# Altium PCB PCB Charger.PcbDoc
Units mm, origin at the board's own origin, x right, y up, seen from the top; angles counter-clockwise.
Board outline 70.24 x 66.94 mm, 2 copper layers (Top Layer, Bottom Layer), stack 1.57 mm thick; 196 components, 95 nets, 576 pads, 0 vias.
Unrouted connection lines stored in the file: 426.
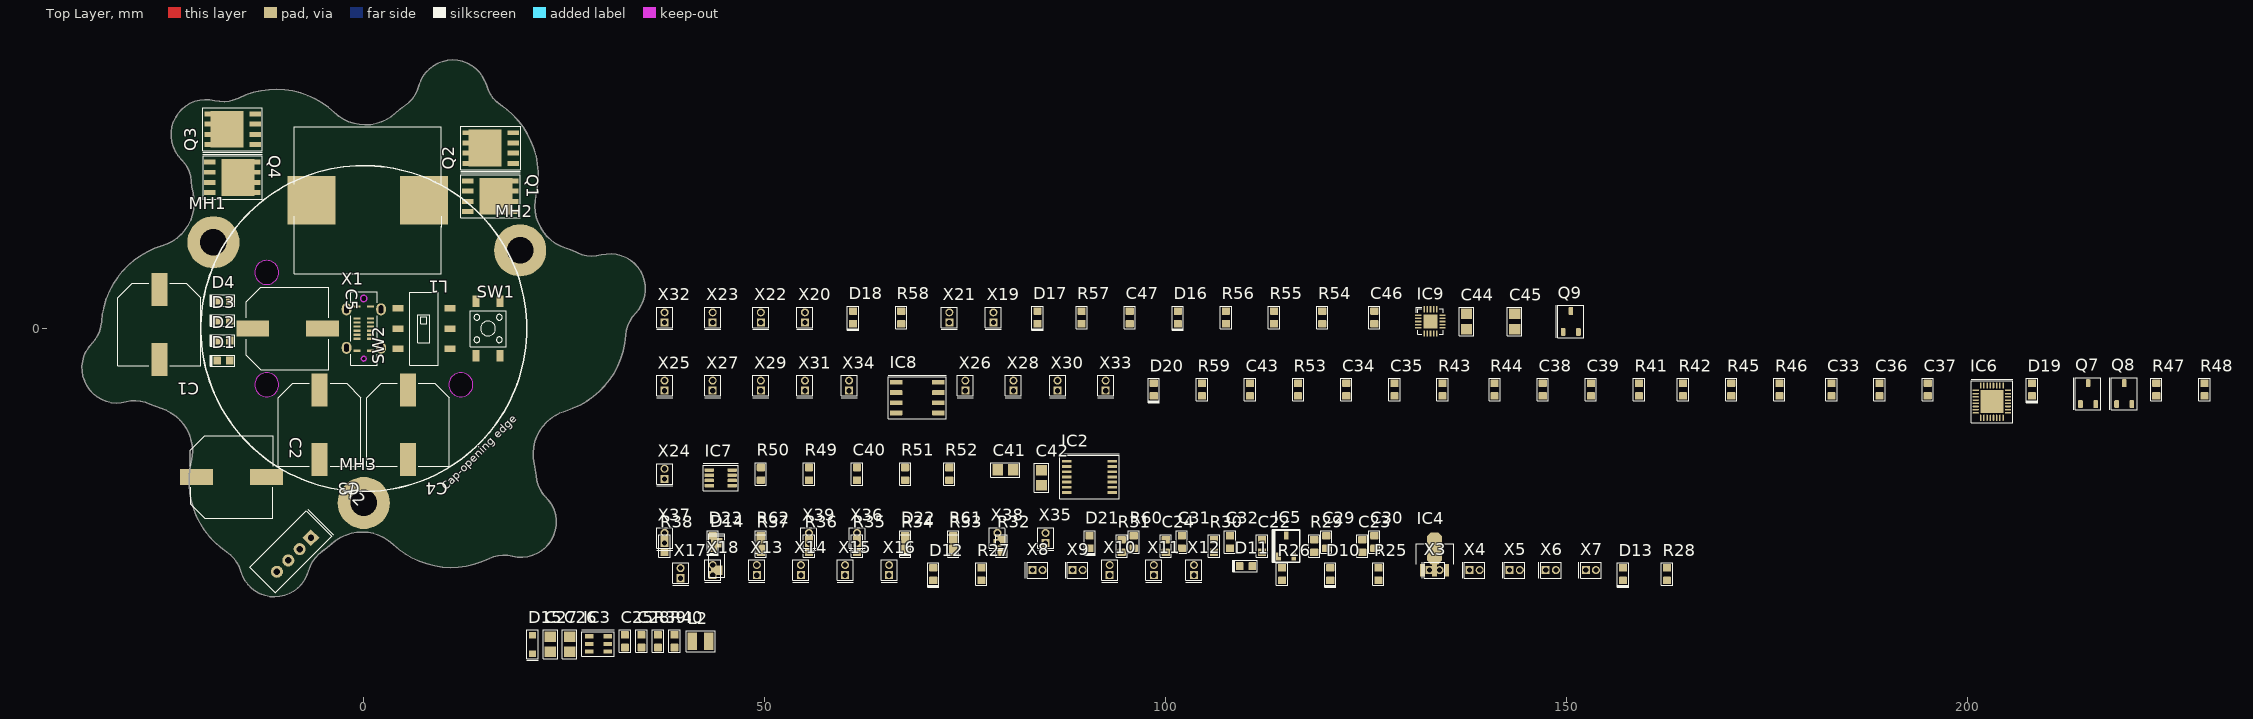
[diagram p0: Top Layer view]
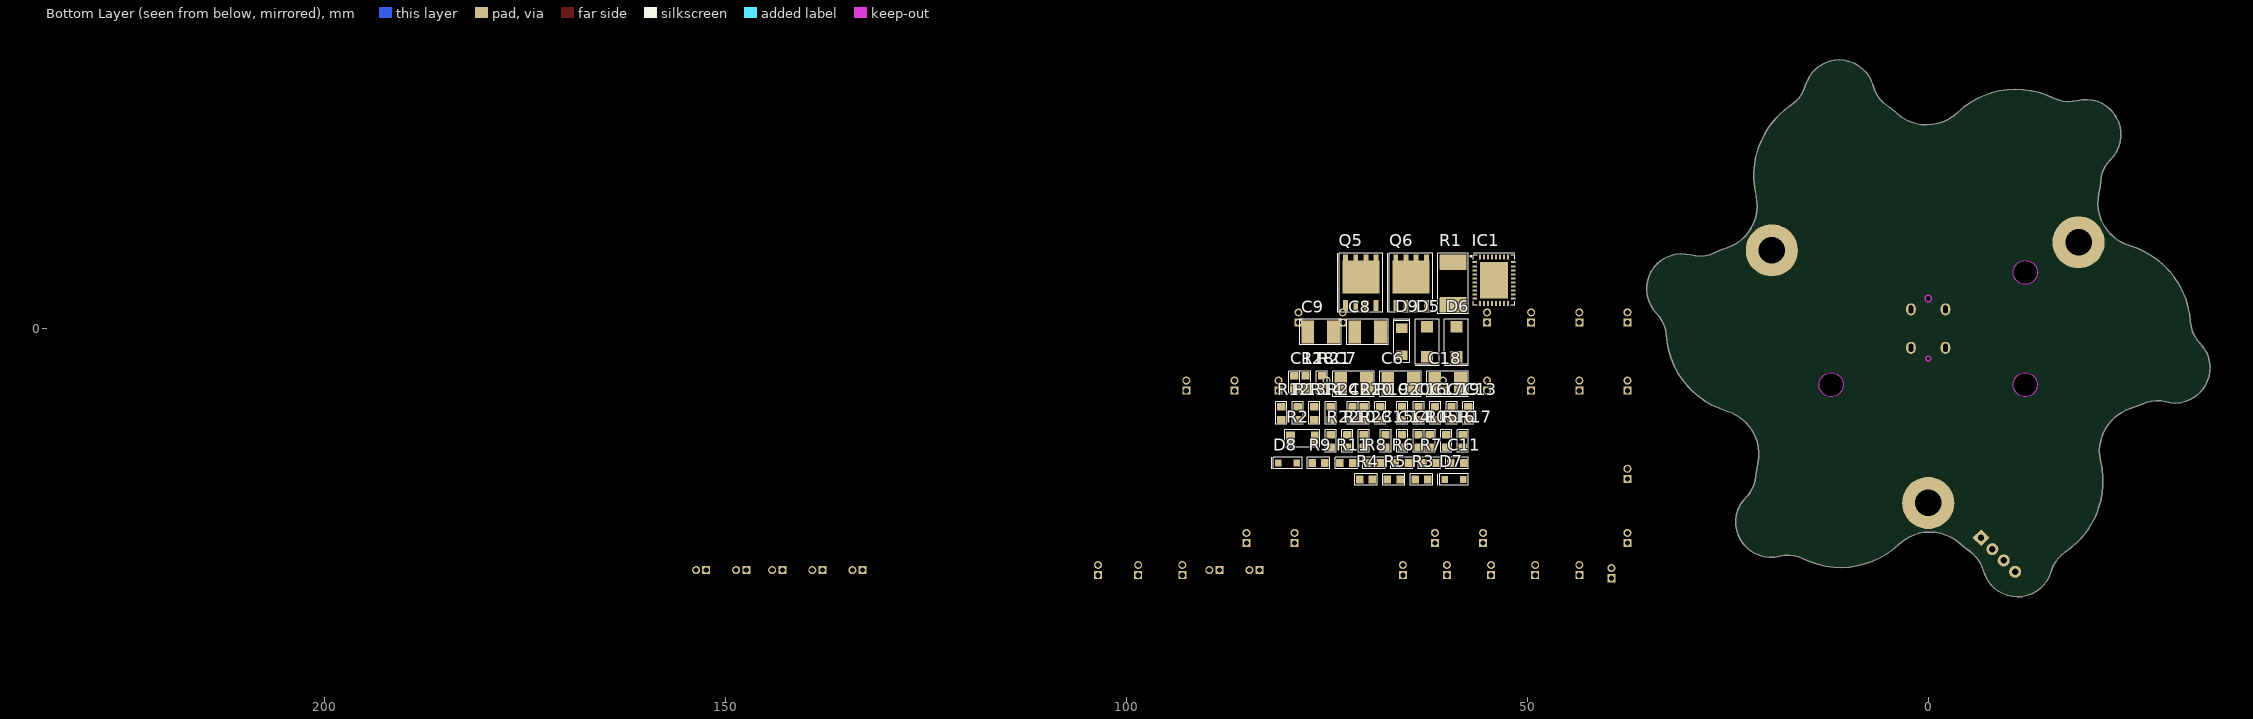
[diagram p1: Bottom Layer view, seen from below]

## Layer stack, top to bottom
Top Solder: solder mask 0.0102, Solder Resist, Dk 3.5
Top Layer: signal copper 0.0356
Dielectric 1: core 1.4986, Core-043, Dk 4.3
Bottom Layer: signal copper 0.0356
Bottom Solder: solder mask 0.0102, Solder Resist, Dk 3.5

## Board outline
331 vertices, not listed, extent -35.137,-33.454 35.107,33.486
cut-out: 10.61,-6.994 ccw(c12.11,-6.994) 12.11,-8.494 ccw(c12.11,-6.994) 13.61,-6.994 ccw(c12.11,-6.994) 12.11,-5.494 ccw(c12.11,-6.994)
cut-out: -13.61,6.994 ccw(c-12.11,6.994) -12.11,5.494 ccw(c-12.11,6.994) -10.61,6.994 ccw(c-12.11,6.994) -12.11,8.494 ccw(c-12.11,6.994)
cut-out: -13.609,-6.996 ccw(c-12.109,-6.996) -12.109,-8.496 ccw(c-12.109,-6.996) -10.609,-6.996 ccw(c-12.109,-6.996) -12.109,-5.496 ccw(c-12.109,-6.996)

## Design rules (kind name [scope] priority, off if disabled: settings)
Clearance [All] p1: gap=0.254 ignorepadtopadclearanceinfootprint=FALSE
PolygonConnect [All] p1: connectstyle=Relief reliefconductorwidth=0.254 reliefentries=4 polygonreliefangle="90 Angle" airgapwidth=0.254
RoutingVias [All] p1: holewidth=0.711 width=1.27 viastyle="Through Hole" minholewidth=0.711 minwidth=1.27 maxholewidth=0.711 maxwidth=1.27
SolderMaskExpansion [All] p1: expansion=0.102 istentingtop=FALSE
SupplyNets "Schematic Supply Nets_5" [InNet('LDO_3V3')] p1: voltage=0.000
SupplyNets "Schematic Supply Nets_4" [InNet('5V_SoC')] p2: voltage=0.000
SupplyNets "Schematic Supply Nets_3" [InNet('12V')] p3: voltage=0.000
SupplyNets "Schematic Supply Nets_2" [InNet('5V')] p4: voltage=0.000
SupplyNets "Schematic Supply Nets_1" [InNet('3V3')] p5: voltage=0.000
SupplyNets "Schematic Supply Nets" [InNet('GND')] p6: voltage=0.000
Width [All] p1: maxlimit=0.254 minlimit=0.254 preferedwidth=0.254
30 further rules are at their usual default settings.

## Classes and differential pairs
component class "USB PROTECTION": C44 C45 C46 C47 D16 D17 D18 IC9 Q9 R54 R55 R56 R57 R58 X19 X20 X21 X22 X23 X32
component class "USB PD": C33 C34 C35 C36 C37 C38 C39 C43 D19 D20 IC6 IC8 Q7 Q8 R41 R42 R43 R44 R45 R46 R47 R48 R53 R59 X25 X26 X27 X28 X29 X30 X31 X33 X34
component class "POWER PATH SWITCH": C40 C41 C42 IC7 Q5 Q6 R49 R50 R51 R52 X24
component class "POWER DISTRIBUTION": C25 C26 C27 C28 C29 C30 C31 C32 D15 D21 D22 D23 IC3 IC4 IC5 L2 R39 R40 R60 R61 R62 X35 X36 X37 X38 X39
component class "BATTERY LEVEL INDICATOR": C22 C23 C24 D14 IC2 R29 R30 R31 R32 R33 R34 R35 R36 R37 R38
component class CHARGER: C1 C2 C3 C4 C5 C6 C7 C8 C9 C10 C11 C12 C13 C14 C15 C16 C17 C18 C19 C20 C21 D5 D6 D7 D8 D9 D10 D11 D12 D13 IC1 L1 Q1 Q2 Q3 Q4 R1 R2 R3 R4 R5 R6 R7 R8 R9 R10 R11 R12 R13 R14 R15 R16 R17 R18 R19 R20 R21 R22 R23 R24 R25 R26 R27 R28 X3 X4 X5 X6 X7 X8 X9 X10 X11 X12 X13 X14 X15 X16 X17 X18
component class Arhitecture: D1 D2 D3 D4 MH1 MH2 MH3 SW1 SW2 X1 X2

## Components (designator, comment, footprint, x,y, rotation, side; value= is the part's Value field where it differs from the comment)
C1 "EEHZA1J560P" CAP_SMD_10X10.2 -25.5,0.5 r270 top
C2 "EEHZA1J560P" CAP_SMD_10X10.2 -16.5,-18.5 r0 top
C3 "EEHZA1J560P" CAP_SMD_10X10.2 -5.5,-12 r270 top
C4 "EEHZA1J560P" CAP_SMD_10X10.2 5.5,-12 r270 top
C5 "EEHZA1J560P" CAP_SMD_10X10.2 -9.5,0 r0 top
C6 "HMK325C7475KN-TE" CAP_1210 65.787,-6.899 r180 bottom
C7 "HMK325C7475KN-TE" CAP_1210 71.645,-6.899 r180 bottom
C8 "HMK325C7475KN-TE" CAP_1210 69.903,-0.441 r180 bottom
C9 "HMK325C7475KN-TE" CAP_1210 75.761,-0.441 r180 bottom
C10 "CL10A106MA8NRNC" "CAP 0603" 63.538,-14.015 r90 bottom
C11 "CL10A106MA8NRNC" "CAP 0603" 58.729,-16.773 r180 bottom
C12 "CC0603KRX7R0BB104" "CAP 0603" 79.054,-6.699 r90 bottom
C13 "CC0603KRX7R0BB104" "CAP 0603" 57.364,-10.557 r90 bottom
C14 "CC0603KRX7R0BB104" "CAP 0603" 65.596,-14.015 r90 bottom
C15 "CC0603KRX7R0BB104" "CAP 0603" 67.654,-14.015 r90 bottom
C16 "CL10B474KA8NNNC" "CAP 0603" 63.538,-10.557 r90 bottom
C17 "CL10B474KA8NNNC" "CAP 0603" 61.48,-10.557 r90 bottom
C18 "HMK325C7475KN-TE" CAP_1210 59.929,-6.899 r180 bottom
C19 "CL10A106MA8NRNC" "CAP 0603" 59.422,-10.557 r90 bottom
C20 "CL10A106MA8NRNC" "CAP 0603" 65.596,-10.557 r90 bottom
C21 "CC0603KRX7R9BB153" "CAP 0603" 71.77,-10.557 r90 bottom
C22 "CGA0603X5R226M100JT" "CAP 0603" 112.006,-27.118 r90 top
C23 "CGA0603X5R226M100JT" "CAP 0603" 124.506,-27.118 r90 top
C24 "CGA0603X5R226M100JT" "CAP 0603" 100.006,-27.118 r90 top
C25 "CL10A105KB8NNNC" "CAP 0603" 32.561,-38.983 r90 top
C26 "CL21A475KBQNNNE" CAP_0805 25.67,-39.358 r90 top
C27 "CL21A475KBQNNNE" CAP_0805 23.262,-39.358 r90 top
C28 "CL10A106MA8NRNC" "CAP 0603" 34.619,-38.983 r90 top
C29 "CL10A106MA8NRNC" "CAP 0603" 120.006,-26.618 r90 top
C30 "CL10A106MA8NRNC" "CAP 0603" 126.006,-26.618 r90 top
C31 "CL10A106MA8NRNC" "CAP 0603" 102.006,-26.618 r90 top
C32 "CL10A106MA8NRNC" "CAP 0603" 108.006,-26.618 r90 top
C33 "CL10A106MA8NRNC" "CAP 0603" 183.006,-7.618 r90 top
C34 "CL10A106MA8NRNC" "CAP 0603" 122.506,-7.618 r90 top
C35 "CL10A106MA8NRNC" "CAP 0603" 128.506,-7.618 r90 top
C36 "CL10A105KB8NNNC" "CAP 0603" 189.006,-7.618 r90 top
C37 "CL10A106MA8NRNC" "CAP 0603" 195.006,-7.618 r90 top
C38 "CL10B221KB8NNNC" "CAP 0603" 147.006,-7.618 r90 top
C39 "CL10B221KB8NNNC" "CAP 0603" 153.006,-7.618 r90 top
C40 "CL10A105KB8NNNC" "CAP 0603" 61.506,-18.118 r90 top
C41 "CC0805KKX7R0BB105" Cap_0805 80.006,-17.618 r0 top
C42 "CC0805KKX7R0BB105" Cap_0805 84.506,-18.618 r90 top
C43 "CL10A106MA8NRNC" "CAP 0603" 110.506,-7.618 r90 top
C44 "CC0805KKX7R0BB105" Cap_0805 137.506,0.882 r90 top
C45 "CC0805KKX7R0BB105" Cap_0805 143.506,0.882 r90 top
C46 "CL10A106MA8NRNC" "CAP 0603" 126.006,1.382 r90 top
C47 "CC0603KRX7R0BB104" "CAP 0603" 95.506,1.382 r90 top
D1 "XL-1608SURC-06" DIODE_0603 -17.5,-4 r0 top
D2 "XL-1608SURC-06" DIODE_0603 -17.5,-1.5 r0 top
D3 "XL-1608SURC-06" DIODE_0603 -17.5,1 r0 top
D4 "XL-1608SURC-06" DIODE_0603 -17.5,3.5 r0 top
D5 "SS210F" SMAF 62.487,-1.641 r90 bottom
D6 "SS210F" SMAF 58.829,-1.641 r90 bottom
D7 "1N5819WS" SOD-323 59.129,-18.831 r180 bottom
D8 "1N5819WS" SOD-323 79.877,-16.773 r180 bottom
D9 "BZT52C3V0" SOD-123 65.645,-3.341 r90 bottom
D10 "XL-1608UOC-06" DIODE_0603 120.506,-30.618 r90 top
D11 "XL-1608UOC-06" DIODE_0603 110.006,-29.618 r0 top
D12 "PSC-1608U52GC-G4" DIODE_0603 71.006,-30.618 r90 top
D13 "XL-1608UOC-06" DIODE_0603 157.006,-30.618 r90 top
D14 "BZT52C3V0" SOD-123 44.006,-30.118 r90 top
D15 "1N5819WS" SOD-323 21.029,-39.383 r90 top
D16 "XL-1608SURC-06" DIODE_0603 101.506,1.382 r90 top
D17 "XL-1608UOC-06" DIODE_0603 84.006,1.382 r90 top
D18 "XL-1608UOC-06" DIODE_0603 61.006,1.382 r90 top
D19 "PSC-1608U52GC-G4" DIODE_0603 208.006,-7.618 r90 top
D20 "Diode LED Green" DIODE_0603 98.506,-7.618 r90 top
D21 "XL-1608UOC-06" DIODE_0603 90.506,-26.618 r90 top
D22 "XL-1608UOC-06" DIODE_0603 67.506,-26.618 r90 top
D23 "XL-1608UOC-06" DIODE_0603 43.506,-26.618 r90 top
IC1 "BQ25756RRVR" VQFN-36(5x6) 54.131,6.017 r180 bottom
IC2 "LM339LVPWR" TSSOP-14 90.5,-18.5 r0 top
IC3 "LV2842XLVDDCR" SOT-23-6 28.103,-38.383 r0 top
IC4 "Pd = 0.7W" SOT-89-3 132.006,-30.118 r0 top
IC5 "Pd = 100mW" "SOT-23 123" 115.006,-27.118 r0 top
IC6 "TPS26750SRSMR" "VQFN (32) 4x4" 203.006,-9.118 r0 top
IC7 "LM74502HQDDFRQ1" SOT-23-8 44.506,-18.618 r0 top
IC8 "CAT24C512WI-GT3" SOIC8 69.006,-8.618 r0 top
IC9 "TPD4S480RUKR" "WQFN (20)" 133.006,0.882 r0 top
L1 "MTF1810-150M" MTF1810-150M 0.5,16 r180 top
L2 "FTC252012S100MBCA" "IND 1008" 42,-39 r0 top
MH1 "M?" "M3 Plated" -18.75,10.75 r0 top locked
MH2 "M?" "M3 Plated" 19.5,9.75 r0 top locked
MH3 "M?" "M3 Plated" 0,-21.75 r0 top locked
Q1 "CRSM038N10N4" "DFN-8 (5x6)" 16.5,16.5 r270 top
Q2 "CRSM038N10N4" "DFN-8 (5x6)" 15.118,22.506 r90 top
Q3 "CRSM038N10N4" "DFN-8 (5x6)" -17.061,24.854 r90 top
Q4 "CRSM038N10N4" "DFN-8 (5x6)" -15.678,18.847 r270 top
Q5 "E060N2P3HL1" "DFN-8 (5x6)" 70.745,6.417 r180 bottom
Q6 "E060N2P3HL1" "DFN-8 (5x6)" 64.487,6.417 r180 bottom
Q7 "2N7002" "SOT-23 GSD" 215.006,-8.118 r0 top
Q8 "2N7002" "SOT-23 GSD" 219.506,-8.118 r0 top
Q9 "HL2310A" "SOT-23 GSD" 150.506,0.882 r0 top
R1 "Pd = 1W" RES_2512 59.229,5.617 r90 bottom
R2 "Pd = 0.125 W" RES_1206 78.051,-13.715 r180 bottom
R3 "0603WAF100JT5E" RES_0603 63.187,-18.831 r180 bottom
R4 "0603WAF100JT5E" RES_0603 70.103,-18.831 r180 bottom
R5 "0603WAF100JT5E" RES_0603 66.645,-18.831 r180 bottom
R6 "0603WAF100JT5E" RES_0603 65.645,-16.773 r180 bottom
R7 "0603WAF1004T5E" RES_0603 62.187,-16.773 r180 bottom
R8 "0603WAF3483T5E" RES_0603 69.103,-16.773 r180 bottom
R9 "0603WAF3012T5E" RES_0603 76.019,-16.773 r180 bottom
R10 "0603WAF220KT5E" RES_0603 72.435,-14.015 r90 bottom
R11 "0603WAF220KT5E" RES_0603 72.561,-16.773 r180 bottom
R12 "0603WAF220KT5E" RES_0603 80.667,-10.557 r90 bottom
R13 "0603WAF220KT5E" RES_0603 78.609,-10.557 r90 bottom
R14 "0603WAF220KT5E" RES_0603 76.551,-10.557 r90 bottom
R15 "0603WAF220KT5E" RES_0603 62.145,-14.015 r90 bottom
R16 "RT0603BRD07249KL" RES_0603 60.087,-14.015 r90 bottom
R17 "RT0603BRD0713K8L" RES_0603 58.029,-14.015 r90 bottom
R18 "I_IN_LIM = 5.5 A" RES_0603 77.661,-6.699 r90 bottom
R19 "F_sw = 200 kHz" RES_0603 68.319,-10.557 r90 bottom
R20 "I_CHG_MAX = 15 A" RES_0603 70.377,-10.557 r90 bottom
R21 "0603WAF0000T5E" RES_0603 75.603,-6.699 r90 bottom
R22 "0603WAF0000T5E" RES_0603 74.493,-14.015 r90 bottom
R23 "0603WAF5761T5E" RES_0603 70.377,-14.015 r90 bottom
R24 "Place NTC next to hottest fet." RES_0603 74.493,-10.557 r90 bottom
R25 "0603WAF4532T5E" RES_0603 126.506,-30.618 r90 top
R26 "0603WAF1002T5E" RES_0603 114.506,-30.618 r90 top
R27 "0603WAF1002T5E" RES_0603 77.006,-30.618 r90 top
R28 "0603WAF4532T5E" RES_0603 162.506,-30.618 r90 top
R29 "0603WAF2001T5E" RES_0603 118.506,-27.118 r90 top
R30 "0603WAF8662T5E" RES_0603 106.006,-27.118 r90 top
R31 "0603WAF5101T5E" RES_0603 94.506,-27.118 r90 top
R32 "FRC0603F7870TS" RES_0603 79.506,-27.118 r90 top
R33 "0603WAF5101T5E" RES_0603 73.506,-27.118 r90 top
R34 "RC0603FR-07698RL" RES_0603 67.506,-27.118 r90 top
R35 "0603WAF5101T5E" RES_0603 61.506,-27.118 r90 top
R36 "RT0603BRD07626RL" RES_0603 55.506,-27.118 r90 top
R37 "0603WAF5101T5E" RES_0603 49.506,-27.118 r90 top
R38 "FRC0603F1132TS" RES_0603 37.506,-27.118 r90 top
R39 "0603WAF1473T5E" RES_0603 36.677,-38.983 r90 top
R40 "0603WAF1002T5E" RES_0603 38.735,-38.983 r90 top
R41 "0603WAF4700T5E" RES_0603 159.006,-7.618 r90 top
R42 "0603WAF1003T5E" RES_0603 164.506,-7.618 r90 top
R43 "0603WAF1003T5E" RES_0603 134.506,-7.618 r90 top
R44 "0603WAF4700T5E" RES_0603 141.006,-7.618 r90 top
R45 "0603WAF1002T5E" RES_0603 170.506,-7.618 r90 top
R46 "0603WAF1002T5E" RES_0603 176.506,-7.618 r90 top
R47 "0603WAF1002T5E" RES_0603 223.506,-7.618 r90 top
R48 "0603WAF1002T5E" RES_0603 229.506,-7.618 r90 top
R49 "0603WAF1003T5E" RES_0603 55.506,-18.118 r90 top
R50 "FRC0603F2321TS" RES_0603 49.506,-18.118 r90 top
R51 "0603WAF0000T5E" RES_0603 67.506,-18.118 r90 top
R52 "0603WAF0000T5E" RES_0603 73.006,-18.118 r90 top
R53 "0603WAF1003T5E" RES_0603 116.506,-7.618 r90 top
R54 "0603WAF0000T5E" RES_0603 119.506,1.382 r90 top
R55 "0603WAF0000T5E" RES_0603 113.506,1.382 r90 top
R56 "0603WAF1002T5E" RES_0603 107.506,1.382 r90 top
R57 "0603WAF8662T5E" RES_0603 89.506,1.382 r90 top
R58 "0603WAF4122T5E" RES_0603 67.006,1.382 r90 top
R59 "0603WAF1002T5E" RES_0603 104.506,-7.618 r90 top
R60 "0603WAF1002T5E" RES_0603 96.006,-26.618 r90 top
R61 "0603WAF1002T5E" RES_0603 73.506,-26.618 r90 top
R62 "0603WAF1002T5E" RES_0603 49.506,-26.618 r90 top
SW1 "TS4560TP" TS4560TP 15.5,0 r90 top
SW2 "SS-3235S-L3" SS-3235S-L3 7.5,0 r90 top
X1 "TYPE-C 16P LTH6.8" "TYPE-C 16P LTH6.8" 0,0 r90 top
X2 "B4B-PH-K-S(LF)(SN)" B4B-PH-K-S(LF)(SN) -8.707,-28.207 r45 top
X3 "ZX-PZ1.27-1-2PZZ" "Pin header 1x2 1.27mmP THT Vertical" 133.506,-30.118 r0 top
X4 "ZX-PZ1.27-1-2PZZ" "Pin header 1x2 1.27mmP THT Vertical" 138.506,-30.118 r0 top
X5 "ZX-PZ1.27-1-2PZZ" "Pin header 1x2 1.27mmP THT Vertical" 143.506,-30.118 r0 top
X6 "ZX-PZ1.27-1-2PZZ" "Pin header 1x2 1.27mmP THT Vertical" 148.006,-30.118 r0 top
X7 "ZX-PZ1.27-1-2PZZ" "Pin header 1x2 1.27mmP THT Vertical" 153.006,-30.118 r0 top
X8 "ZX-PZ1.27-1-2PZZ" "Pin header 1x2 1.27mmP THT Vertical" 84.006,-30.118 r0 top
X9 "ZX-PZ1.27-1-2PZZ" "Pin header 1x2 1.27mmP THT Vertical" 89.006,-30.118 r0 top
X10 "ZX-PZ1.27-1-2PZZ" "Pin header 1x2 1.27mmP THT Vertical" 93.006,-30.118 r90 top
X11 "ZX-PZ1.27-1-2PZZ" "Pin header 1x2 1.27mmP THT Vertical" 98.506,-30.118 r90 top
X12 "ZX-PZ1.27-1-2PZZ" "Pin header 1x2 1.27mmP THT Vertical" 103.506,-30.118 r90 top
X13 "ZX-PZ1.27-1-2PZZ" "Pin header 1x2 1.27mmP THT Vertical" 49.006,-30.118 r90 top
X14 "ZX-PZ1.27-1-2PZZ" "Pin header 1x2 1.27mmP THT Vertical" 54.506,-30.118 r90 top
X15 "ZX-PZ1.27-1-2PZZ" "Pin header 1x2 1.27mmP THT Vertical" 60.006,-30.118 r90 top
X16 "ZX-PZ1.27-1-2PZZ" "Pin header 1x2 1.27mmP THT Vertical" 65.506,-30.118 r90 top
X17 "ZX-PZ1.27-1-2PZZ" "Pin header 1x2 1.27mmP THT Vertical" 39.5,-30.5 r90 top
X18 "ZX-PZ1.27-1-2PZZ" "Pin header 1x2 1.27mmP THT Vertical" 43.506,-30.118 r90 top
X19 "ZX-PZ1.27-1-2PZZ" "Pin header 1x2 1.27mmP THT Vertical" 78.506,1.382 r90 top
X20 "ZX-PZ1.27-1-2PZZ" "Pin header 1x2 1.27mmP THT Vertical" 55.006,1.382 r90 top
X21 "ZX-PZ1.27-1-2PZZ" "Pin header 1x2 1.27mmP THT Vertical" 73.006,1.382 r90 top
X22 "ZX-PZ1.27-1-2PZZ" "Pin header 1x2 1.27mmP THT Vertical" 49.506,1.382 r90 top
X23 "ZX-PZ1.27-1-2PZZ" "Pin header 1x2 1.27mmP THT Vertical" 43.506,1.382 r90 top
X24 "ZX-PZ1.27-1-2PZZ" "Pin header 1x2 1.27mmP THT Vertical" 37.506,-18.118 r90 top
X25 "ZX-PZ1.27-1-2PZZ" "Pin header 1x2 1.27mmP THT Vertical" 37.506,-7.118 r90 top
X26 "ZX-PZ1.27-1-2PZZ" "Pin header 1x2 1.27mmP THT Vertical" 75.006,-7.118 r90 top
X27 "ZX-PZ1.27-1-2PZZ" "Pin header 1x2 1.27mmP THT Vertical" 43.506,-7.118 r90 top
X28 "ZX-PZ1.27-1-2PZZ" "Pin header 1x2 1.27mmP THT Vertical" 81.006,-7.118 r90 top
X29 "ZX-PZ1.27-1-2PZZ" "Pin header 1x2 1.27mmP THT Vertical" 49.506,-7.118 r90 top
X30 "ZX-PZ1.27-1-2PZZ" "Pin header 1x2 1.27mmP THT Vertical" 86.506,-7.118 r90 top
X31 "ZX-PZ1.27-1-2PZZ" "Pin header 1x2 1.27mmP THT Vertical" 55.006,-7.118 r90 top
X32 "ZX-PZ1.27-1-2PZZ" "Pin header 1x2 1.27mmP THT Vertical" 37.506,1.382 r90 top
X33 "ZX-PZ1.27-1-2PZZ" "Pin header 1x2 1.27mmP THT Vertical" 92.506,-7.118 r90 top
X34 "ZX-PZ1.27-1-2PZZ" "Pin header 1x2 1.27mmP THT Vertical" 60.506,-7.118 r90 top
X35 "ZX-PZ1.27-1-2PZZ" "Pin header 1x2 1.27mmP THT Vertical" 85.006,-26.118 r90 top
X36 "ZX-PZ1.27-1-2PZZ" "Pin header 1x2 1.27mmP THT Vertical" 61.506,-26.118 r90 top
X37 "ZX-PZ1.27-1-2PZZ" "Pin header 1x2 1.27mmP THT Vertical" 37.506,-26.118 r90 top
X38 "ZX-PZ1.27-1-2PZZ" "Pin header 1x2 1.27mmP THT Vertical" 79.006,-26.118 r90 top
X39 "ZX-PZ1.27-1-2PZZ" "Pin header 1x2 1.27mmP THT Vertical" 55.506,-26.118 r90 top

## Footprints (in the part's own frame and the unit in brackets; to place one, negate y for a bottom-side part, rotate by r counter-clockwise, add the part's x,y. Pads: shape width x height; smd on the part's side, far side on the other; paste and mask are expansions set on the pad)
B4B-PH-K-S(LF)(SN) [mm] "JST PH 2.00mm 1x4 THT Vertical"
  rect 1.5x1.5 hole 0.8: 1(3,0)
  round 1.5 hole 0.8: 2(1,0) 3(-1,0) 4(-3,0)
  silkscreen extent -5,-1.7 5.2,2.8, body extent -4.95,-1.7 4.95,2.8, height 6.01
"CAP 0603" [mm] "CAP 0603"
  rrect20% 0.94x1.02 smd: 1(-0.79,0) 2(0.79,0)
  silkscreen extent -1.4,-0.7 1.4,0.7, body extent -0.8,-0.5 0.8,0.47, height 0.81
CAP_0805 [mm]
  rect 1.312x1.396 smd: 1(-0.948,0) 2(0.948,0)
  silkscreen extent -1.8,-0.9 1.8,0.9, body extent -1.05,-0.67 1.05,0.67, height 1.35
Cap_0805 [mm]
  rect 1.312x1.396 smd: 1(-0.948,0) 2(0.948,0)
  silkscreen extent -1.8,-0.9 1.8,0.9, body extent -1.05,-0.67 1.05,0.67, height 1.35
CAP_1210 [mm] "Cap SMD 1210"
  rect 1.6x2.904 smd: 1(-1.6,0) 2(1.6,0)
  silkscreen extent -2.6,-1.6 2.6,1.6, body extent -1.6,-1.35 1.6,1.35, height 2.51
CAP_SMD_10X10.2 [mm] "Elko, radial SMD FI10xH10.2mm"
  rect 4.1x2 smd: +(-4.35,0) -(4.35,0)
  silkscreen extent -5.15,-5.15 5.15,5.15, body extent -5.85,-5.15 5.85,5.15, height 10.21
"DFN-8 (5x6)" [mil] "Mosfet SMD footprint"
  rect 24x55 smd paste-3937.01 mask+2: D(-75,83) D(-25,83) D(25,83) D(75,83) G(75,-139) S(-75,-139) S(-25,-139) S(25,-139)
  rect 181.1x161.42 smd paste-3937.01 mask+2: D(0,0)
  silkscreen extent -114,-173 106,118, body extent -101,-150 101,93, height 42
DIODE_0603 [mm] "RES 0603"
  rrect20% 0.94x1.02 smd: A(0.79,0) K(-0.79,0)
  silkscreen extent -1.63,-0.7 1.4,0.7, body extent -0.8,-0.4 0.8,0.4, height 0.46
"IND 1008" [mm] "Power inductor SMD 1008"
  rect 1.2x2.2 smd: 1(-1.028,0) 2(1.028,0)
  silkscreen extent -1.8,-1.3 1.8,1.3, body extent -1.26,-1 1.26,1, height 1.21
"M3 Plated" [mm] "M3 hole"
  round 6.5 hole 3.3: 1(0,0)
MTF1810-150M [mm] "Inductor SMD 18.2x18.2x8.9 mm"
  rect 6x6 smd: 1(-7,0) 2(7,0)
  silkscreen extent -9.14,-9.14 9.14,9.14, body extent -9.2,-9.11 9.1,9.11, height 9.02
"Pin header 1x2 1.27mmP THT Vertical" [mm] "Pin header 1x2 1.27mmP THT Vertical"
  rect 1x1 hole 0.65: 1(-0.635,0)
  round 1 hole 0.65: 2(0.635,0)
  silkscreen extent -1.5,-1 1.28,1, body extent -1.28,-1 1.28,1, height 4.91
RES_0603 [mm] "RES 0603"
  rrect20% 0.94x1.02 smd: 1(-0.79,0) 2(0.79,0)
  silkscreen extent -1.4,-0.7 1.4,0.7, body extent -0.8,-0.4 0.8,0.4, height 0.46
RES_1206 [mm]
  rrect14% 1.09x1.77 smd: 1(-1.465,0)
  rrect14% 0.94x1.77 smd: 2(1.54,0)
  silkscreen extent -2.2,-1.1 2.2,1.1, body extent -1.55,-0.77 1.55,0.78, height 0.56
RES_2512 [mm] "Generic resistor footprint"
  rrect7% 1.9x3.37 smd: 1(-2.66,0) 2(2.66,0)
  silkscreen extent -3.8,-1.9 3.8,1.9, body extent -3.18,-1.57 3.17,1.58, height 0.75
SMAF [mm] "DIODE SMAF"
  rect 1.46x1.53 smd: A(1.875,0) K(-1.875,0)
  silkscreen extent -3,-1.5 2.8,1.5, body extent -2.3,-1.3 2.3,1.3, height 1.11
SOD-123 [mm] "Diode FP"
  rect 1.2x1.4 smd: A(0,0) K(3.4,0)
  silkscreen extent -0.9,-1 4.5,1, body extent -0.13,-0.77 3.52,0.77, height 1.44
SOD-323 [mm] "Diode package"
  rect 0.8x0.9 smd: A(1.15,0) K(-1.15,0)
  silkscreen extent -2,-0.7 1.8,0.7, body extent -1.25,-0.63 1.25,0.63, height 1.11
SOIC8 [mm]
  rrect25% 1.58x0.59 smd: 1(-2.625,1.905) 2(-2.625,0.635) 3(-2.625,-0.635) 4(-2.625,-1.905) 5(2.625,-1.905) 6(2.625,-0.635) 7(2.625,0.635) 8(2.625,1.905)
  silkscreen extent -3.6,-2.6 3.6,2.8, body extent -3,-2.5 3,2.5, height 1.75
"SOT-23 123" [mm] "Nmos SOT23"
  rect 0.583x1 smd: 1(-0.95,-1.3) 2(0.95,-1.3) 3(0,1.3)
  silkscreen extent -1.7,-2 1.7,2, body extent -1.51,-1.26 1.51,1.26, height 1.12
"SOT-23 GSD" [mm] "Nmos SOT23 Gate Source Drain"
  rrect50% 0.583x1 smd: D(0,1.3) G(-0.95,-1.3) S(0.95,-1.3)
  silkscreen extent -1.8,-2 1.6,2, body extent -1.51,-1.26 1.51,1.26, height 1.12
SOT-23-6 [mm]
  rect 1.072x0.532 smd: 1(0,0) 2(0,-0.95) 3(0,-1.9) 4(2.298,-1.9) 5(2.298,-0.95) 6(2.298,0)
  silkscreen extent -0.9,-2.5 3.1,0.8, body extent -0.3,-2.35 2.5,0.55, height 1.2
SOT-23-8 [mm] "IC package"
  rrect50% 1.198x0.431 smd mask+0.05: 1(-1.424,0.975) 2(-1.424,0.325) 3(-1.424,-0.325) 4(-1.424,-0.975) 5(1.424,-0.975) 6(1.424,-0.325) 7(1.424,0.325) 8(1.424,0.975)
  silkscreen extent -2.2,-1.6 2.2,1.8, body extent -1.47,-1.47 1.47,1.47, height 1.09
SOT-89-3 [mm] "SOT-89-3"
  rect 0.672x1.575 smd paste+0 mask+0.051: 1(0,0) 2(1.5,0) 3(3,0)
  oct 1.9x4 smd paste+0 mask+0.05: 2(1.5,2.712)
  silkscreen extent -0.8,0.7 3.9,3.3, body extent -0.75,-0.45 3.75,3.8, height 1.55
SS-3235S-L3 [mm] "Slide switch"
  rect 0.8x1.35 smd: 1(-2.54,3.25) 1(-2.54,-3.25) 2(0,3.25) 2(0,-3.25) 3(2.54,3.25) 3(2.54,-3.25)
  silkscreen extent -4.55,-1.8 4.55,1.8, body extent -4.6,-3.45 4.5,3.45, height 7.56
TS4560TP [mm] "Switch tactile 4.5x4.5mm 6mmH"
  rect 1.4x0.9 smd: 1(-3.4,1.5) 2(3.4,1.5) 3(-3.4,-1.5) 4(3.4,-1.5)
  silkscreen extent -2.25,-2.25 2.25,2.25, body extent -3.25,-2.25 3.25,2.25, height 7.51
TSSOP-14 [mm] "TSSOP-14"
  rect 1.2x0.35 smd: 1(-2.825,1.95) 2(-2.825,1.3) 3(-2.825,0.65) 4(-2.825,0) 5(-2.825,-0.65) 6(-2.825,-1.3) 7(-2.825,-1.95) 8(2.825,-1.95) 9(2.825,-1.3) 10(2.825,-0.65) 11(2.825,0) 12(2.825,0.65) 13(2.825,1.3) 14(2.825,1.95)
  silkscreen extent -3.7,-2.7 3.7,2.9, body extent -3.2,-2.5 3.2,2.5, height 1.2
"TYPE-C 16P LTH6.8" [mm] "USB C 16P SMD Vertical 6.8mmH"
  rect 0.3x0.87 smd mask+0.051: A1(-2.75,0.865) A4(-1.25,0.865) A5(-0.75,0.865) A6(-0.25,0.865) A7(0.25,0.865) A8(0.75,0.865) A9(1.25,0.865) A12(2.75,0.865) B1(2.75,-0.865) B4(1.25,-0.865) B5(0.75,-0.865) B6(0.25,-0.865) B7(-0.25,-0.865) B8(-0.75,-0.865) B9(-1.25,-0.865) B12(-2.75,-0.865)
  oval 1.5x1.2 hole 0.61 slot 1 at 0 deg: CASE(-2.4,-2.15) CASE(-2.4,2.15) CASE(2.4,-2.15)
  oval 1.5x1.2 hole 0.61 slot 1 at 0 deg copper offset 0,0: CASE(2.4,2.15)
  Keep-Out Layer board cut-out: -3.45,0 -3.48,-0.13 -3.563,-0.234 -3.683,-0.292 -3.817,-0.292 -3.937,-0.234 -4.02,-0.13 -4.05,0 -4.05,0 -4.02,0.13 -3.937,0.235 -3.817,0.293 -3.683,0.293 -3.563,0.235 -3.48,0.13 -3.45,0
  Keep-Out Layer board cut-out: 4.15,0 4.111,-0.174 4,-0.313 3.839,-0.39 3.661,-0.39 3.501,-0.313 3.39,-0.174 3.35,0 3.35,0 3.39,0.174 3.501,0.313 3.661,0.39 3.839,0.39 4,0.313 4.111,0.174 4.15,0
  Keep-Out Layer circle w0.025: c-3.75,0 r0.3
  Keep-Out Layer circle w0.025: c3.75,0 r0.4
  Keep-Out Layer region: -3.45,0 -3.48,-0.13 -3.563,-0.234 -3.683,-0.292 -3.817,-0.292 -3.937,-0.234 -4.02,-0.13 -4.05,0 -4.05,0 -4.02,0.13 -3.937,0.235 -3.817,0.293 -3.683,0.293 -3.563,0.235 -3.48,0.13 -3.45,0
  Keep-Out Layer region: 4.15,0 4.111,-0.174 4,-0.313 3.839,-0.39 3.661,-0.39 3.501,-0.313 3.39,-0.174 3.35,0 3.35,0 3.39,0.174 3.501,0.313 3.661,0.39 3.839,0.39 4,0.313 4.111,0.174 4.15,0
  silkscreen extent -4.57,-1.65 4.57,1.65, body extent -4.47,-2.3 4.47,2.3, height 6.51
"VQFN (32) 4x4" [mm] "VQFN 32 pin 4x4mm"
  rect 0.78x0.2 smd paste+0 mask+0: 1(-2.016,1.4)
  rrect100% 0.78x0.2 smd paste+0 mask+0: 2(-2.016,1) 3(-2.016,0.6) 4(-2.016,0.2) 5(-2.016,-0.2) 6(-2.016,-0.6) 7(-2.016,-1) 8(-2.016,-1.4) 17(2.016,-1.4) 18(2.016,-1) 19(2.016,-0.6) 20(2.016,-0.2) 21(2.016,0.2) 22(2.016,0.6) 23(2.016,1) 24(2.016,1.4)
  rrect100% 0.2x0.78 smd paste+0 mask+0: 9(-1.4,-2.016) 10(-1,-2.016) 11(-0.6,-2.016) 12(-0.2,-2.016) 13(0.2,-2.016) 14(0.6,-2.016) 15(1,-2.016) 16(1.4,-2.016) 25(1.4,2.016) 26(1,2.016) 27(0.6,2.016) 28(0.2,2.016) 29(-0.2,2.016) 30(-0.6,2.016) 31(-1,2.016) 32(-1.4,2.016)
  rect 2.85x2.85 smd paste-1000 mask+0: 33(0,0)
  silkscreen extent -2.6,-2.6 2.6,2.8, body extent -2.96,-2.96 2.96,2.96, height 0.25
VQFN-36(5x6) [mm] "TI IC"
  rect 0.6x0.25 smd mask+0.07: 1(-2.4,2.25)
  rect 0.6x0.25 smd paste+0 mask+0.07: 2(-2.4,1.75) 3(-2.4,1.25) 4(-2.4,0.75) 5(-2.4,0.25) 6(-2.4,-0.25) 7(-2.4,-0.75) 8(-2.4,-1.25) 9(-2.4,-1.75) 10(-2.4,-2.25) 19(2.4,-2.25) 20(2.4,-1.75) 21(2.4,-1.25) 22(2.4,-0.75) 23(2.4,-0.25) 24(2.4,0.25) 25(2.4,0.75) 26(2.4,1.25) 27(2.4,1.75) 28(2.4,2.25)
  rect 0.25x0.6 smd paste+0 mask+0.07: 11(-1.75,-2.9) 12(-1.25,-2.9) 13(-0.75,-2.9) 14(-0.25,-2.9) 15(0.25,-2.9) 16(0.75,-2.9) 17(1.25,-2.9) 18(1.75,-2.9) 29(1.75,2.9) 30(1.25,2.9) 31(0.75,2.9) 32(0.25,2.9) 33(-0.25,2.9) 34(-0.75,2.9) 35(-1.25,2.9) 36(-1.75,2.9)
  rect 3.5x4.5 smd paste-100 mask+0.051: 37(0,0)
  silkscreen extent -2.91,-3.1 2.6,3.4, body extent -2.51,-3 2.51,3.02, height 0.76
"WQFN (20)" [mm] "IC footprint"
  rect 0.8x0.2 smd mask+0.051: 1(-1.5,0.8) 2(-1.5,0.4) 3(-1.5,0) 4(-1.5,-0.4) 5(-1.5,-0.8) 11(1.5,-0.8) 12(1.5,-0.4) 13(1.5,0) 14(1.5,0.4) 15(1.5,0.8)
  rect 0.2x0.8 smd mask+0.051: 6(-0.8,-1.5) 7(-0.4,-1.5) 8(0,-1.5) 9(0.4,-1.5) 10(0.8,-1.5) 16(0.8,1.5) 17(0.4,1.5) 18(0,1.5) 19(-0.4,1.5) 20(-0.8,1.5)
  rect 1.7x1.7 smd paste-100 mask+0.051: 21(0,0)
  silkscreen extent -1.8,-1.6 1.6,1.8, body extent -1.5,-1.5 1.5,1.5, height 0.8

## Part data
C1 C2 C3 C4 C5: "Cap AL-EL 56uF 63V 30mR 1.8Ar SMD 10x10.2mm", Capacitance=56u, Manufacturer=Panasonic, Supplier Part Number 1=?, Voltage Rating=63V
C6 C7 C8 C9 C18: "Cap 4.7uF 100V 1210 X7R", Capacitance=4u7, Case Code (Imperial)=1210, Manufacturer="Taiyo Yuden", Supplier Part Number 1=?, Voltage Rating=100V
C10 C11 C19 C20 C28 C29 C30 C31 C32 C33 C34 C35 C37 C43 C46: "Cap 10uF 25V 0603 X5R", Capacitance=10u, Case Code (Imperial)=0603, Manufacturer=Samsung, Supplier Part Number 1=?, Voltage Rating=25V
C12 C13 C14 C15 C47: "Cap 100nF 100V 0603 X7R", Capacitance=100n, Case Code (Imperial)=0603, Manufacturer=YAGEO, Supplier Part Number 1=?, Voltage Rating=100V
C16 C17: "Cap 470nF 25V 0603 X7R", Capacitance=470n, Case Code (Imperial)=0603, Manufacturer=Samsung, Supplier Part Number 1=?, Voltage Rating=25V
C21: "Cap 15nF 50V 0603 X7R", Capacitance=15n, Case Code (Imperial)=0603, Manufacturer=Yageo, Manufacturer Part Number=CC0603KRX7R9BB104, Supplier Part Number 1=?, Voltage Rating=50V
C22 C23 C24: "Cap 22uF 10V 0603 X5R", Capacitance=22u, Case Code (Imperial)=0603, Manufacturer=HRE, Supplier Part Number 1=?, Voltage Rating=10V
C25 C36 C40: "Cap 1uF 50V 0603 X5R", Capacitance=1u, Case Code (Imperial)=0603, Manufacturer=Samsung, Supplier Part Number 1=?, Voltage Rating=50V
C26 C27: "Cap 4.7uF 50V 0805 X5R", Capacitance=4u7, Case Code (Imperial)=0805, Manufacturer=Samsung, Supplier Part Number 1=?, Voltage Rating=50V
C38 C39: "Cap 220pF 50V 0603 X7R", Capacitance=220p, Case Code (Imperial)=0603, Manufacturer=Samsung, Supplier Part Number 1=?, Voltage Rating=50V
C41 C42 C44 C45: "Cap 1uF 100V 0805 X7R", Capacitance=1u, Case Code (Imperial)=0805, Manufacturer=Yageo, Supplier Part Number 1=?, Voltage Rating=100V
D1 D2 D3 D4 D16: "LED Red 0603 25mA", Manufacturer=Xinglight
D5 D6: "Schottky 100V 2A 850mVf SMAF", Forward Current=2A, Manufacturer=GOODWORK, Reverse Voltage=100V, Supplier Part Number 1=?
D7 D8 D15: "Schottky 40V 1A 600mVf SOD-323", Forward Current=1A, Manufacturer="Guangdong Hottech", Reverse Voltage=40V, Supplier Part Number 1=?
D9 D14: "Zener 3.0V 500mW SOD-123", Manufacturer="Shandong Jingdao Microelectronics", Power Rating=500mW, Reverse Voltage=3V, Supplier Part Number 1=?
D10 D11 D13 D17 D18 D21 D22 D23: "LED Orange 0603 20mA", Manufacturer=XINGLIGHT
D12 D19: "LED Green 0603 20mA", Manufacturer=HONGLITRONIC
D20: "Generic green LED symbol"
IC1: "Charger IC", Manufacturer="Texas Instruments"
IC2: "Comparator Quad 1.65~5.5V TSSOP-14", Manufacturer="Texas Instruments"
IC3: "Step-down converter 4~40Vin 600mAout Adjustible SOT23-6", Manufacturer="Texas Instruments"
IC4: library part 78L05, "LDO 5V 100mA 30Vin", Manufacturer=UMW
IC5: library part LR7533-T, "LDO 24Vin 3.3Vout fixed", Manufacturer=LR
IC6: "USB PD IC EPR 240W", Manufacturer="Texas Instruments"
IC7: "High-side switch controller IC 3.2~65V Reverse polarity protection", Manufacturer="Texas Instruments"
IC8: "EEPROM SOIC-8", Manufacturer=OnSemi
IC9: "USB PD protection IC", Manufacturer="Texas Instruments"
L1: "Inductor 15uH 22Asat 10mR SMD 18x18x9 mm", Inductance=15uH, Manufacturer=COILMX, Resistance=10mR, Saturation current=22Asat, Supplier Part Number 1=?
L2: "Inductor 10uH 1.6Asat 330mR", Inductance=10uH, Manufacturer=cjiang, Resistance=330mR, Saturation current=1.6Asat, Supplier Part Number 1=?
MH1 MH2 MH3: library part "Mounting hole", "Generic mounting hole symbol"
Q1 Q2 Q3 Q4: "Nmos 100V 100A 3.6mR DFN-8(5x6)", Manufacturer=CRMICRO, Voltage=100V
Q5 Q6: "Nmos 60V 180A 2.3mR PDFN5x6-8", Manufacturer=Existar, Voltage=60V
Q7 Q8: "nMOS 60V 115mA SOT-23", Manufacturer="Jiangsu Changjing Electronics Technology Co., Ltd.", Voltage=60V
Q9: "nMOS 60V 3A SOT-23", Manufacturer=hongjiacheng, Voltage=60V
R1: library part RLM25FEER005, "Res 5mR 2512 1% 2W", Case Code (Imperial)=2512, Manufacturer="TA-I Tech", Power Rating=2W, Resistance=5mR, Resistance Tolerance=1%, Supplier Part Number 1=?
R2: library part FRM121WFR005TM, "Res 5mR 1206 1% 1W", Case Code (Imperial)=1206, Manufacturer=FOJAN, Power Rating=1W, Resistance=5mR, Resistance Tolerance=1%, Supplier Part Number 1=?
R3 R4 R5 R6: "Res 10R 0603 1% 100mW 75V", Case Code (Imperial)=0603, Manufacturer=Uni-Royal, Power Rating=100mW, Resistance=10R, Resistance Tolerance=1%, Supplier Part Number 1=?
R7: "Res 1M 0603 1% 100mW 75V", Case Code (Imperial)=0603, Manufacturer=Uni-Royal, Power Rating=100mW, Resistance=1M, Resistance Tolerance=1%, Supplier Part Number 1=?
R8: "Res 348k 0603 1% 100mW 75V", Case Code (Imperial)=0603, Manufacturer=Uni-Royal, Power Rating=100mW, Resistance=348k, Resistance Tolerance=1%, Supplier Part Number 1=?
R9: "Res 30k1 0603 1% 100mW 75V", Case Code (Imperial)=0603, Manufacturer=Uni-Royal, Power Rating=100mW, Resistance=30k1, Resistance Tolerance=1%, Supplier Part Number 1=?
R10 R11 R12 R13 R14 R15: "Res 2R2 0603 1% 100mW 75V", Case Code (Imperial)=0603, Manufacturer=Uni-Royal, Power Rating=100mW, Resistance=2R2, Resistance Tolerance=1%, Supplier Part Number 1=?
R16: "Res 249K 0603 0.1% 100mW 75V", Case Code (Imperial)=0603, Manufacturer=YAGEO, Power Rating=100mW, Resistance=249K, Resistance Tolerance=0%1, Supplier Part Number 1=?
R17: "Res 13.8k 0603 0.1% 100mW 75V", Case Code (Imperial)=0603, Manufacturer=YAGEO, Power Rating=100mW, Resistance=13k8, Resistance Tolerance=0%1, Supplier Part Number 1=?
R18: library part FRC0603F3741TS, "Res 3K74 0603 1% 100mW 75V", Case Code (Imperial)=0603, Manufacturer=FOJAN, Power Rating=100mW, Resistance=3k74, Resistance Tolerance=1%, Supplier Part Number 1=?
R19: library part 0603WAF2003T5E, "Res 200K 0603 1% 100mW 75V", Case Code (Imperial)=0603, Manufacturer=UNI-ROYAL, Power Rating=100mW, Resistance=200k, Resistance Tolerance=1%, Supplier Part Number 1=?
R20: library part 0603WAF3321T5E, "Res 3k32 0603 1% 100mW 75V", Case Code (Imperial)=0603, Manufacturer=UNI-ROYAL, Power Rating=100mW, Resistance=3k32, Resistance Tolerance=1%, Supplier Part Number 1=?
R21 R22 R51 R52 R54 R55: "Res 0R 0603 1% 100mW 75V", Case Code (Imperial)=0603, Manufacturer=UNI-ROYAL, Power Rating=100mW, Resistance=0R, Resistance Tolerance=1%, Supplier Part Number 1=?
R23: "Res 5k76 0603 1% 100mW 75V", Case Code (Imperial)=0603, Manufacturer=Uni-Royal, Power Rating=100mW, Resistance=5k76, Resistance Tolerance=1%, Supplier Part Number 1=?
R24: library part NCP18XH103F03RB, "NTC 10k 0603 1% 3455K", Case Code (Imperial)=0603, Manufacturer=Murata, Resistance=10k, Supplier Part Number 1=?
R25 R28: "Res 45k3 0603 1% 100mW 75V", Case Code (Imperial)=0603, Manufacturer=Uni-Royal, Power Rating=100mW, Resistance=45k3, Resistance Tolerance=1%, Supplier Part Number 1=?
R26 R27 R40 R45 R46 R47 R48 R56 R59 R60 R61 R62: "Res 10k 0603 1% 100mW 75V", Case Code (Imperial)=0603, Manufacturer=Uni-Royal, Power Rating=100mW, Resistance=10k, Resistance Tolerance=1%, Supplier Part Number 1=?
R29: "Res 2k 0603 1% 100mW 75V", Case Code (Imperial)=0603, Manufacturer=Uni-Royal, Power Rating=100mW, Resistance=2k, Resistance Tolerance=1%, Supplier Part Number 1=?
R30 R57: "Res 86k6 0603 1% 100mW 75V", Case Code (Imperial)=0603, Manufacturer=Uni-Royal, Power Rating=100mW, Resistance=86k6, Resistance Tolerance=1%, Supplier Part Number 1=?
R31 R33 R35 R37: "Res 5k1 0603 1% 100mW 75V", Case Code (Imperial)=0603, Manufacturer=Uni-Royal, Power Rating=100mW, Resistance=5k1, Resistance Tolerance=1%, Supplier Part Number 1=?
R32: "Res 787R 0603 1% 100mW 75V", Case Code (Imperial)=0603, Manufacturer=FOJAN, Power Rating=100mW, Resistance=787R, Resistance Tolerance=1%, Supplier Part Number 1=?
R34: "Res 698R 0603 1% 100mW 75V", Case Code (Imperial)=0603, Manufacturer=YAGEO, Power Rating=100mW, Resistance=698R, Resistance Tolerance=1%, Supplier Part Number 1=?
R36: "Res 626R 0603 1% 100mW 75V", Case Code (Imperial)=0603, Manufacturer=YAGEO, Power Rating=100mW, Resistance=626R, Resistance Tolerance=1%, Supplier Part Number 1=?
R38: "Res 11k3 0603 1% 100mW 75V", Case Code (Imperial)=0603, Manufacturer=Fojan, Power Rating=100mW, Resistance=11k3, Resistance Tolerance=1%, Supplier Part Number 1=?
R39: "Res 147k 0603 1% 100mW 75V", Case Code (Imperial)=0603, Manufacturer=Uni-Royal, Power Rating=100mW, Resistance=147k, Resistance Tolerance=1%, Supplier Part Number 1=?
R41 R44: "Res 470R 0603 1% 100mW 75V", Case Code (Imperial)=0603, Manufacturer=Uni-Royal, Power Rating=100mW, Resistance=470R, Resistance Tolerance=1%, Supplier Part Number 1=?
R42 R43 R49 R53: "Res 100k 0603 1% 100mW 75V", Case Code (Imperial)=0603, Manufacturer=Uni-Royal, Power Rating=100mW, Resistance=100k, Resistance Tolerance=1%, Supplier Part Number 1=?
R50: "Res 2k32 0603 1% 100mW 75V", Case Code (Imperial)=0603, Manufacturer=Uni-Royal, Power Rating=100mW, Resistance=2k32, Resistance Tolerance=1%, Supplier Part Number 1=?
R58: "Res 41k2 0603 1% 100mW 75V", Case Code (Imperial)=0603, Manufacturer=Uni-Royal, Power Rating=100mW, Resistance=41k2, Resistance Tolerance=1%, Supplier Part Number 1=?
SW1: "Switch Tactile SMD 4.5x4.5mm 6mmH SPST", Manufacturer="Shou Han"
SW2: "Switch Slide SMD 9.1x3.5mm 6.6mmH", Manufacturer="XKB Connection"
X1: "USB-C 16P SMD Vertical 6.50mmH", Manufacturer="Shou Han"
X2: "Pin header 1x4 2.00mmP THT Vertical JST PH", Manufacturer=JST
X3 X4 X5 X6 X7 X8 X9 X10 X11 X12 X13 X14 X15 X16 X17 X18 X19 X20 X21 X22 X23 X24 X25 X26 X27 X28 X29 X30 X31 X32 X33 X34 X35 X36 X37 X38 X39: "Pin header 1x2 1.27mmP THT Vertical", Manufacturer=Megastar

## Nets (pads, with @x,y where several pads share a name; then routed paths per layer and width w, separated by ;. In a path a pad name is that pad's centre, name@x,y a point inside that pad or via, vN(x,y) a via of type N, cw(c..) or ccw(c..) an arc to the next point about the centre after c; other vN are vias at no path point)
3V3: C32.2 C33.2 D23.A IC5.2 IC6.32 X37.1
5V: C30.2 C37.2 D22.A IC4.1 IC6.28 IC6.29 SW1.1 SW1.2 X36.1
5V_SoC: C22.2 C23.1 IC2.3 R29.2 SW1.3 SW1.4
12V: C28.2 C29.2 C31.2 D8.A D21.A IC4.3 IC5.3 L2.2 R39.2 X35.1
ACN: C13.2 C16.2 IC1.29 R4.1 X16.2
ACOV: IC1.35 R8.1 R9.2
ACP: C12.1 C16.1 IC1.30 R3.1 X16.1
ACUV: IC1.34 R7.1 R8.2
ADCIN1: IC6.2 R41.1 R43.2 X33.1
ADCIN2: IC6.3 R42.1 R44.2 X34.1
BTST1: C10.1 D5.K IC1.26
BTST2: C11.2 D6.K IC1.20
C_CC1: IC9.4 R54.1 X1.A5 X19.1
C_CC2: IC9.5 R55.1 X1.B5 X20.1
CC1: C38.2 IC6.24 IC9.12 X30.1
CC2: C39.2 IC6.25 IC9.11 X31.1
DRV_SUP: C19.2 D7.K D8.K IC1.23 R14.1 R15.2 X5.1
EPR_BLK_G: IC9.17 Q9.G
ERP_EN: IC6.7 IC9.16 X32.1
FB: IC1.12 R16.1 R17.2 X15.1
FB_12V: IC3.3 R39.1 R40.2 X39.1
FBG: IC1.11 R17.1
FSW_SYNC: IC1.36 R19.2
G_H1: Q1.G R10.2 X3.1
G_H2: Q2.G R13.2 X4.1
G_L1: Q3.G R11.2 X13.1
G_L2: Q4.G R12.2 X14.1
GATE: IC7.6 R51.1 R52.1 X24.1
GND: C1.- C2.- C3.- C4.- C5.- C6.1 C7.1 C8.1 C9.1 C12.2 C13.1 C14.2 C15.1 C18.1 C19.1 C20.1 C21.1 C22.1 C23.2 C24.1 C26.1 C27.1 C28.1 C29.1 C30.1 C31.1 C32.1 C33.1 C34.1 C35.1 C36.1 C37.1 C38.1 C39.1 C41.1 C42.1 C43.1 C44.1 C45.1 C46.1 C47.1 D1.K D2.K D3.K D4.K D9.A D14.A D15.A D19.K IC1.7 IC1.15 IC1.16 IC1.17 IC1.22 IC1.31 IC1.37 IC2.12 IC3.2 IC4.2 IC5.1 IC6.11 IC6.12 IC6.14 IC6.19 IC6.33 IC7.2 IC7.3 IC8.1 IC8.2 IC8.3 IC8.4 IC8.7 IC9.8 IC9.13 IC9.18 IC9.21 MH2.1 Q3.S Q4.S Q7.S Q8.S R9.1 R18.1 R19.1 R20.1 R24.1 R25.2 R26.2 R28.2 R38.1 R40.1 R43.1 R44.1 R50.1 R57.2 R58.2 R59.2 R60.2 R61.2 R62.2 X1.A1 X1.A12 X1.B1 X1.B12 X1.CASE X2.3 X5.2 X6.2 X7.2 X8.2 X9.2 X10.2 X11.2 X12.2 X13.2 X14.2 X15.2 X17.2 X19.2 X20.2 X21.2 X22.2 X23.2 X25.2 X26.2 X27.2 X28.2 X29.2 X30.2 X31.2 X32.2 X33.2 X34.2 X35.2 X36.2 X37.2 X38.2 X39.2
HIDRV1: IC1.27 R10.1
HIDRV2: IC1.19 R13.1
ICHG: IC1.9 R20.2
ILIM_HIZ: IC1.10 R18.2
IN1+: IC2.5 R30.1 R32.2
IN1-: D14.K IC2.4 IC2.6 IC2.8 IC2.10 R29.1
IN2+: IC2.7 R32.1 R34.2
IN3+: IC2.9 R34.1 R36.2
IN4+: IC2.11 R36.1 R38.2
LDO_1V5: C35.2 IC6.4 X27.1
LDO_3V3: C34.2 C43.2 C46.2 D20.A IC6.1 IC8.8 IC9.10 R41.2 R42.2 R45.2 R46.2 R47.2 R48.2 R53.2 R56.2 X26.1
LODRV1: IC1.25 R11.1
LODRV2: IC1.21 R12.1
NetC25_1: C25.1 IC3.1
NetD1_A: D1.A R31.2
NetD2_A: D2.A R33.2
NetD3_A: D3.A R35.2
NetD4_A: D4.A R37.2
NetD5_A: D5.A R14.2
NetD6_A: D6.A R15.1
NetD10_K: D10.K R25.1
NetD11_K: D11.K R26.1
NetD12_A: D12.A R27.1
NetD13_K: D13.K R28.1
NetD16_A: D16.A R56.1
NetD17_K: D17.K R57.1
NetD18_K: D18.K R58.1
NetD20_K: D20.K R59.1
NetD21_K: D21.K R60.1
NetD22_K: D22.K R61.1
NetD23_K: D23.K R62.1
NetIC6_20: IC6.20 Q7.G
NetMH3_1: MH3.1 SW2.1
NetQ5_G: Q5.G R51.2
NetQ6_G: Q6.G R52.2
NetQ7_D: Q7.D Q8.G R47.1
nFLT: D16.K IC9.9 X23.1
nPG: D12.K IC1.6
OUT1: IC2.2 R31.1
OUT2: IC2.1 R33.1
OUT3: IC2.14 R35.1
OUT4: IC2.13 R37.1
OV: IC7.7 R49.1 R50.2
PACK+: C24.2 C26.2 C27.2 D10.A IC3.4 IC3.5 MH1.1 R1.2 R6.2 R16.2 R30.2 SW2.2 X11.1
PP_EN: D19.A IC7.1 Q8.D R48.1 X25.1
REGN: C20.2 D7.A D11.A IC1.24 R23.2 R27.2 X10.1
RPD_G1: IC9.7 R54.2
RPD_G2: IC9.6 R55.2
SCL: IC6.16 IC8.6 R21.1 R46.1 X2.2 X7.1 X29.1
SCL_BQ: IC1.1 R21.2
SDA: IC6.15 IC8.5 R22.1 R45.1 R53.1 X2.4 X12.1 X28.1
SDA_BQ: IC1.2 R22.2
SOURCE: IC7.8 Q5.S Q6.S X24.2
SRN: C15.2 C17.2 IC1.13 R6.1 X18.2
SRP: C14.1 C17.1 IC1.14 R5.1 X18.1
SW: C25.2 D15.K IC3.6 L2.1 X38.1
SW1: C10.2 IC1.28 L1.1 Q1.S Q3.D X3.2 X8.1
SW2: C11.1 IC1.18 L1.2 Q2.S Q4.D X4.2 X9.1
TS: C21.2 D9.K IC1.8 R23.1 R24.2 X17.1
V_CHG_IN: C18.2 C42.2 D13.A IC1.32 IC1.33 Q6.D R2.1 R3.2 R7.2 X6.1
V_HB_IN: C1.+ C6.2 C7.2 Q1.D R2.2 R4.2
V_HB_OUT: C2.+ C3.+ C4.+ C5.+ C8.2 C9.2 Q2.D R1.1 R5.2
VBIAS: C47.2 IC9.3
VBUS: C40.2 C41.2 C44.2 D17.A IC7.5 IC9.20 Q5.D Q9.D R49.2 X1.A4 X1.A9 X1.B4 X1.B9 X21.1
VBUS_LV: C36.2 C45.2 D18.A IC6.26 IC6.27 IC9.19 Q9.S X22.1
VCAP: C40.1 IC7.4
pads on no net: IC1.3 IC1.4 IC1.5 IC6.5 IC6.6 IC6.8 IC6.9 IC6.10 IC6.13 IC6.17 IC6.18 IC6.21 IC6.22 IC6.23 IC6.30 IC6.31 IC9.1 IC9.2 IC9.14 IC9.15 SW2.3 X1.A6 X1.A7 X1.A8 X1.B6 X1.B7 X1.B8 X2.1

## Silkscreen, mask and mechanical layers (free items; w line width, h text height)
Top Overlay:
  circle w0.2: c0,0 r20.32
  text "Cap-opening edge" at 10.257,-20.214 h1 r45
Board:
  drawing of 334 lines, arcs and shapes, not listed
Dimensions:
  circle w0.1: c0,0 r13.985
  circle w0.1: c0,0 r22.225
